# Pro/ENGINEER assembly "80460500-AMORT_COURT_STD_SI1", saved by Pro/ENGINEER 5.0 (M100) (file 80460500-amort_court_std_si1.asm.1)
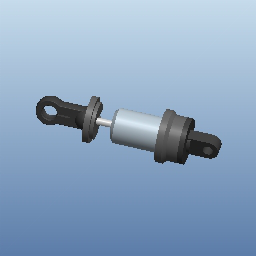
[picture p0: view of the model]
Units: millimeter Newton Second (mmNs); MM, TONNE, HOURS

Other parameters: TRANSLATION1_STATIC_FRICTION, TRANSLATION1_KINETIC_FRICTION, TRANSLATION1_RESTITUTION, TRANSLATION1_MINIMUM_LIMIT, TRANSLATION1_MAXIMUM_LIMIT, TRANSLATION1_ZERO_POSITION

Other components: 80460500-C-AMORT_COURT_STD_SI1, 80160500-TIGE_AMORT_STD_SI1

Other named items: 80460500-C-AMORT_COURT_STD_01, 80160500-TIGE_AMORT_STD_01, A-DROITE, A-DESSUS, A-FACE, A-R0

Family table entries: GENERIC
